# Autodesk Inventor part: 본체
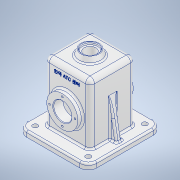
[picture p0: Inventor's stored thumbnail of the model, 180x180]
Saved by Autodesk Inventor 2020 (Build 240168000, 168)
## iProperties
Created: 2022-11
Part Number: 본체
Material: 알루미늄 6061
Document SubType Name: Modeling
Designer: USER
Density: 2.7 g/cm^3
Appearance: 알루미늄 - 평지
Author: USER
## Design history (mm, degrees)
sketch "스케치1"
  geometry: L1 (62, -65)-(-62, -65); L2 (-62, -65)-(-62, 65); L3 (-62, 65)-(62, 65); L4 (62, 65)-(62, -65); L5 (62, -65)-(-62, 65); L6 (-62, -65)-(62, 65); 1 further point
  constraints: 12 end point, 2 midpoint, 2 parallel, 1 horizontal, 1 perpendicular
  dimensions: "d0" = 124 distance of L2.end L3.end; "d1" = 130 distance of L1.end L2.end
extrude "돌출1" new body sketch "스케치1" distance "d2" = 10; taper "d3" = 0 deg
fillet "모깎기1" dims "d4" = 15
sketch "스케치2"
  geometry: L1 (-40, 40)-(40, 40); L2 (40, 40)-(40, -40); L3 (40, -40)-(-40, -40); L4 (-40, -40)-(-40, 40); L5 (-40, 40)-(40, -40); L6 (40, 40)-(-40, -40); 1 further point
  constraints: 12 end point, 2 midpoint, 2 parallel, 1 horizontal, 1 perpendicular
  dimensions: "d5" = 80 distance of L2.end L3.end; "d6" = 80 distance of L1.end L2.end
extrude "돌출2" join sketch "스케치2" distance "d7" = 107; taper "d8" = 0 deg
sketch "스케치6"
  geometry: L1 (80, 0)-(0, 0) reference; L2 (40, 0)-(40, 45); C1 r 27.5 at (40, 45); 1 further point
  constraints: 2 end point, 1 centre point, 1 coincident, 1 midpoint, 1 vertical
  dimensions: "d18" = 45 distance of L2.start L2.end; "d19" = 55 diameter of C1
extrude "돌출6" join sketch "스케치6" distance "d20" = 9; taper "d21" = 0 deg
sketch "스케치7"
  geometry: 1 further point
sketch "스케치8"
  geometry: C1 r 27.5 at (0, 0) reference; C2 r 16 at (0, 0); 1 further point
  constraints: 1 centre point, 1 coincident
  dimensions: "d25" = 32 diameter of C2
extrude "돌출7" cut sketch "스케치8" extent not by distance; stored distance "d26" = 0; taper "d27" = 0 deg
chamfer "모따기2" distance "d28" = 1; stored, may be unused: second distance "d29" = 2, angle "d30" = 45 deg
sketch "스케치9"
  geometry: L1 (117, 40)-(117, -40) reference; L2 (117, 0)-(117, -20); L3 (117, -20)-(127, -16.36); L4 (117, -20)-(136.148, -20); L5 (117, 0)-(127, 0); L6 (127, 0)-(127, -16.36); L7 (117, -40)-(117, 40); L8 (117, 0)-(117, 20); L9 (117, 20)-(127, 16.36); L10 (127, 0)-(127, 16.36); 4 further points
  constraints: 18 end point, 5 symmetric about line, 2 horizontal, 2 point on line, 1 midpoint, 1 perpendicular
revolve "회전1" sketch "스케치9" stored, may be unused: angle "d34" = 90 deg
fillet "모깎기2" dims "d35" = 3
sketch "스케치10"
  geometry: C1 r 14 at (0, 0); 1 further point
  constraints: 1 centre point, 1 coincident
  dimensions: "d36" = 28 diameter of C1
extrude "돌출8" cut sketch "스케치10" distance "d37" = 4; taper "d38" = 0 deg
chamfer "모따기3" distance "d39" = 1; stored, may be unused: second distance "d40" = 2, angle "d41" = 45 deg
sketch "스케치11"
  geometry: C1 r 10.5 at (0, 0); 1 further point
  constraints: 1 centre point, 1 coincident
  dimensions: "d42" = 21 diameter of C1
extrude "돌출9" cut sketch "스케치11" distance "d43" = 32.5; taper "d44" = 0 deg
sketch "스케치12"
  geometry: L1 (32, 32)-(-32, 32); L2 (-32, 32)-(-32, -32); L3 (-32, -32)-(32, -32); L4 (32, -32)-(32, 32); L5 (32, 32)-(-32, -32); L6 (-32, 32)-(32, -32); 1 further point
  constraints: 12 end point, 2 midpoint, 2 parallel, 1 horizontal, 1 perpendicular
  dimensions: "d45" = 64 distance of L3.end L2.end; "d46" = 64 distance of L2.end L1.end
extrude "돌출10" cut sketch "스케치12" distance "d47" = 109; taper "d48" = 0 deg
sketch "스케치13" dims "d49" = 45
  geometry: L1 (0, 0)-(0, 22.5); C1 r 27.5 at (0, 0) reference; C2 r 16 at (0, 0) reference; 2 further points
  constraints: 2 end point, 1 coincident, 1 vertical, 1 vertical alignment, 2 other
hole "구멍1" sketch "스케치13" at (0, 22.5) diameter "d50" = 3.242; stored, may be unused: countersink angle "d54" = 82 deg, drill point angle "d56" = 118 deg; dims "d51" = 8, "d52" = 3.023, "d53" = 2, "d55" = 10
sketch "스케치14"
  geometry: C1 r 4.5 at (-47, 50); A1 r 15 centre (-47, 50) between (-47, 65) and (-62, 50) reference; 1 further point
  constraints: 1 centre point, 1 coincident
  dimensions: "d60" = 9 diameter of C1
extrude "돌출11" cut sketch "스케치14" extent not by distance; stored distance "d61" = 0; taper "d62" = 0 deg
sketch "스케치15"
  geometry: L1 (-62, 10)-(-47, 10); L2 (-62, 10)-(-62, 0); L3 (-62, 10)-(-52, 10); L4 (-52, 10)-(-44.415, 53.017); L5 (-44.415, 53.017)-(-40, 78.055); L6 (-40, 10)-(-40, 117); L7 (-47, 10)-(-40, 10); L8 (-42.5, 0)-(-51.5, 0) reference; 1 further point
  constraints: 14 end point, 2 point on line, 1 parallel
extrude "돌출12" join sketch "스케치15" stored distance "d65" = 10; taper "d66" = 0 deg
fillet "모깎기3" dims "d67" = 3
sketch "스케치16"
  geometry: L1 (47, 10)-(62, 10) reference; L2 (40, 10)-(40, 117) reference; L3 (47, 10)-(62, 10) reference; L4 (62, 10)-(52, 10); L5 (52, 10)-(37.717, 91.001); L6 (52, 10)-(134.251, 10); L7 (47, 10)-(40, 10); 3 further points
  constraints: 8 end point, 2 horizontal, 1 equal length, 1 point on line
  dimensions: "d68" = 10 distance of L1.end L4.end; "d69" = 100 deg angle of L6 L5
extrude "돌출13" join sketch "스케치16" stored distance "d70" = 10; taper "d71" = 0 deg
fillet "모깎기4" dims "d72" = 3
fillet "모깎기5" dims "d73" = 8
fillet "모깎기6" dims "d74" = 8
fillet "모깎기7" dims "d75" = 3
fillet "모깎기8" dims "d76" = 3
fillet "모깎기9" dims "d77" = 3
sketch "스케치17"
  geometry: L1 (8.314, -4)-(54.433, -4); L2 (54.433, -4)-(54.433, -10.004); L3 (54.433, -10.004)-(8.314, -10.004); L4 (8.314, -10.004)-(8.314, -4); L5 (72, -96)-(72, 0) reference; L6 (48.36, 18)-(15.64, 18) reference; 2 further points
  constraints: 2 other
  dimensions: "d80" = 40 distance from line of L5 point (32, -7); "d81" = 25 distance from line of L6 point (32, -7); "d82" = 3 distance from line of L1 point (32, -7); "d83" = 6.00407 distance between parallel lines of L3 L1; "d84" = 23.68594 distance from line of L4 point (32, -7); "d85" = 46.1194 distance between parallel lines of L2 L4
feature "엠보싱1" sketch "스케치17" dims "d86" = 0.5, "d87" = 0
node "솔리드1"
mirror "미러1"
pattern_circular "원형 패턴1" dims angle "d58" = 360 deg
mirror "미러2"
mirror "미러3"
mirror "미러4"
node "투영된 루프1"
feature "A9D066F2-1C7D-4E18-AEED-F7BC21143FA4" dims "d50" = 3.242, "d51" = 8, "d52" = 3.023, "d53" = 2, "d54" = 82 deg, "d55" = 10, "d56" = 118 deg
